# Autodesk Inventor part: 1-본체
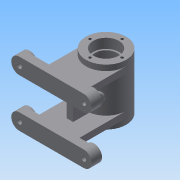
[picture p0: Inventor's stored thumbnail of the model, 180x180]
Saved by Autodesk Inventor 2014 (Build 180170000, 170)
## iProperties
Created: 2015-11
Part Number: 1-본체
Material: Generic
Document SubType Name: Modeling
Designer: 106-16
Density: 1 g/cm^3
Appearance: Default
Author: 106-16
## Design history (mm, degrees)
sketch "스케치1"
  geometry: C1 r 25 at (0, 0); 1 further point
  constraints: 1 centre point, 1 coincident
  dimensions: "d0" = 50 diameter of C1
extrude "돌출1" new body sketch "스케치1" stored distance "d1" = 70; taper "d2" = 0 deg
node "작업 평면2"
  node "작업 평면1"
sketch "스케치2"
  geometry: L1 (-40, 40)-(40, 40); L2 (40, 20)-(-40, 20); L3 (-40, -20)-(40, -20); L4 (40, -40)-(-40, -40); A1 r 10 centre (40, 30) between (40, 20) and (40, 40); A2 r 10 centre (-40, 30) between (-40, 40) and (-40, 20); A3 r 10 centre (40, -30) between (40, -40) and (40, -20); A4 r 10 centre (-40, -30) between (-40, -20) and (-40, -40); 3 further points
  constraints: 8 end point, 8 point on circle, 8 tangent, 4 centre point, 3 parallel, 2 midpoint, 2 vertical alignment, 1 horizontal
  dimensions: "d5" = 80 distance of L1.start L1.end; "d6" = 10 radius of A2; "d7" = 80 distance of L3.start L3.end; "d8" = 10 radius of A4; "d9" = 40 distance from line of point (0, 0) L1; "d10" = 40 distance from line of point (0, 0) L4
extrude "돌출2" join sketch "스케치2" distance "d11" = 10; taper "d12" = 0 deg
sketch "스케치3"
  geometry: L1 (-40, 20)-(40, 20) reference; L2 (40, 40)-(-40, 40) reference; L3 (-40, -40)-(40, -40) reference; L4 (40, -20)-(-40, -20) reference; C1 r 10 at (-40, -30); C2 r 10 at (40, -30); C3 r 10 at (40, 30); C4 r 10 at (-40, 30); A1 r 10 centre (-40, -30) between (-40, -20) and (-40, -40) reference; A2 r 10 centre (40, 30) between (40, 20) and (40, 40) reference; A3 r 10 centre (-40, 30) between (-40, 40) and (-40, 20) reference; A4 r 10 centre (40, -30) between (40, -40) and (40, -20) reference; A5 r 10 centre (-40, -30) between (-40, -20) and (-40, -40) reference; 1 further point
  constraints: 4 centre point, 4 coincident
  dimensions: "d13" = 20 diameter of C1; "d14" = 20 diameter of C4; "d15" = 20 diameter of C3; "d16" = 20 diameter of C2
extrude "돌출3" join sketch "스케치3" distance "d17" = 3; taper "d18" = 0 deg
sketch "스케치4"
  geometry: L1 (40, -20)-(-40, -20) reference; L2 (40, 20)-(-40, 20) reference; L3 (-40, 40)-(40, 40) reference; L4 (-25, 20)-(-25, 28); L5 (-25, 28)-(25, 28); L6 (25, 28)-(25, 20); L7 (-25, -20)-(-25, -28); L8 (-25, -28)-(25, -28); L9 (25, -28)-(25, -20); A1 r 10 centre (-40, 30) between (-40, 40) and (-40, 20) reference; A2 r 10 centre (40, 30) between (40, 20) and (40, 40) reference; 3 further points
  constraints: 12 end point, 5 perpendicular, 4 point on line, 2 midpoint, 2 vertical alignment, 1 parallel
  dimensions: "d19" = 8 distance between parallel lines of L2 L5; "d20" = 50 distance of L4.end L5.end; "d21" = 8 distance of L7.start L7.end; "d22" = 50 distance of L7.end L8.end
extrude "돌출4" join sketch "스케치4" stored distance "d23" = 3; taper "d24" = 0 deg
node "작업 평면4"
  node "작업 평면3"
sketch "스케치5"
  geometry: L1 (40, 40)-(-40, 40) reference; L2 (-40, 20)-(40, 20) reference; L3 (40, -20)-(-40, -20) reference; L4 (-40, -40)-(40, -40) reference; L5 (-4, -20)-(-4, 20); L6 (4, 20)-(4, -20); A1 r 10 centre (-40, 30) between (-40, 40) and (-40, 20) reference; A2 r 10 centre (40, 30) between (40, 20) and (40, 40) reference; A3 r 10 centre (-40, -30) between (-40, -20) and (-40, -40) reference; A4 r 10 centre (40, -30) between (40, -40) and (40, -20) reference; 1 further point
  constraints: 4 end point, 4 point on line, 2 perpendicular
  dimensions: "d26" = 8 distance between parallel lines of L6 L5; "d27" = 4 distance from line of L5 point (0, 0)
extrude "돌출5" join sketch "스케치5" stored distance "d28" = 3; taper "d29" = 0 deg
sketch "스케치6"
  geometry: L1 (40, 20.322)-(40, 0) reference; L2 (12, 13.5)-(28, 13.5); L3 (28, 6.5)-(12, 6.5); L4 (55, 20)-(55, 70) reference; L5 (-15, 70)-(-15, 20) reference; L6 (0, 20.322)-(40, 20.322) reference; L7 (40, 20.322)-(40, 45) reference; L8 (40, 45)-(48, 45) reference; L9 (48, 45)-(48, 45) reference; L10 (40, 45)-(48, 45) reference; L11 (40, 45)-(40, 20.322) reference; L12 (40, 20.322)-(0, 20.322) reference; L13 (0, 20.322)-(0, 45) reference; L14 (-8, 45)-(0, 45) reference; L15 (-8, 45)-(-8, 45) reference; L16 (-8, 45)-(0, 45) reference; L17 (0, 45)-(0, 20.322) reference; L18 (40, -23)-(60, -23) reference; A1 r 3.5 centre (28, 10) between (28, 6.5) and (28, 13.5); A2 r 3.5 centre (12, 10) between (12, 13.5) and (12, 6.5); 3 further points
  constraints: 4 end point, 4 point on circle, 4 tangent, 2 centre point, 2 midpoint, 1 parallel, 1 perpendicular, 1 vertical alignment
  dimensions: "d30" = 23 dimension on A2 A1; "d31" = 3.5 radius of A1; "d32" = 33 vertical distance of A1.centre L18.start
extrude "돌출6" cut sketch "스케치6" stored distance "d33" = 3; taper "d34" = 0 deg
node "작업 평면5"
sketch "스케치7"
  geometry: L1 (-25, -35)-(25, -35) reference; 2 further points
  constraints: 1 other
  dimensions: "d35" = 25 horizontal distance of point (0, 0) L1.start; "d36" = 35 distance from line of point (0, 0) L1
feature "엠보싱1" sketch "스케치7" dims "d37" = 0.5, "d38" = 0
node "작업 평면7"
  node "작업 평면6"
sketch "스케치8"
  geometry: C1 r 5 at (0, 0); 1 further point
  constraints: 1 centre point, 1 coincident
  dimensions: "d40" = 10 diameter of C1
extrude "돌출7" join sketch "스케치8" stored distance "d41" = 3; taper "d42" = 0 deg
node "작업 평면8"
sketch "스케치9"
  geometry: L1 (0, 0)-(25, 0); L2 (0, 0)-(12.5, -21.651); L3 (0, 0)-(0, -25); A1 r 25 centre (0, 0) between (25, 0) and (12.5, -21.651) reference; 2 further points
  constraints: 6 end point, 3 point on circle, 1 coincident, 1 horizontal, 1 perpendicular
  dimensions: "d44" = 30 deg angle of L2 L3
node "작업 평면10"
  node "작업 평면9"
sketch "스케치10"
  geometry: C1 r 6 at (0, 0); 1 further point
  constraints: 1 centre point, 1 coincident
  dimensions: "d46" = 12 diameter of C1
extrude "돌출8" join sketch "스케치10" stored distance "d47" = 3; taper "d48" = 0 deg
sketch "스케치11"
  geometry: C1 r 10 at (0, 0) reference; C2 r 10 at (0, -60) reference; C3 r 10 at (80, 0) reference; C4 r 10 at (80, -60) reference; 5 further points
  constraints: 4 coincident
hole "구멍1" sketch "스케치11" at (0, 0), (0, -60), (80, -60), (80, 0) diameter "d49" = 6; stored, may be unused: countersink angle "d53" = 90 deg, drill point angle "d55" = 0 deg; dims "d50" = 6, "d51" = 12, "d52" = 4, "d54" = 13
hole "구멍2" diameter "d58" = 28; stored, may be unused: countersink angle "d62" = 90 deg, drill point angle "d64" = 0 deg; dims "d56" = 10, "d57" = 10, "d59" = 6, "d60" = 32, "d61" = 12, "d63" = 13
hole "구멍3" diameter "d67" = 28; stored, may be unused: countersink angle "d71" = 90 deg, drill point angle "d73" = 0 deg; dims "d65" = 10, "d66" = 10, "d68" = 6, "d69" = 32, "d70" = 12, "d72" = 13
node "작업 평면11"
sketch "스케치12"
  geometry: L1 (-14, -23)-(14, -23) reference; L2 (14, 23)-(-14, 23) reference; L3 (14, -23)-(14, 23) reference; L4 (-14, -23)-(-14, 23) reference; L5 (0, 21)-(0, -21); L6 (21, 18)-(21, -18); L7 (0, 21)-(18, 21); L8 (0, -21)-(18, -21); A1 r 3 centre (18, 18) between (21, 18) and (18, 21); A2 r 3 centre (18, -18) between (18, -21) and (21, -18); 2 further points
  constraints: 8 end point, 4 point on circle, 4 tangent, 2 centre point, 2 parallel, 2 perpendicular, 1 coincident, 1 equal radius, 1 midpoint
  dimensions: "d75" = 42 distance of L5.start L5.end; "d76" = 42 diameter of L6 L5; "d77" = 3 radius of A1
revolve "회전1" sketch "스케치12" stored, may be unused: angle "d78" = 90 deg
sketch "스케치13"
  geometry: C1 r 16 at (0, 0) reference; C2 r 25 at (0, 0) reference; A1 r 20 centre (0, 0) between (0, 20) and (20, 0); 2 further points
  constraints: 4 point on circle, 2 horizontal alignment, 2 vertical alignment, 1 centre point, 1 coincident
  dimensions: "d79" = 40 diameter of A1
hole "구멍4" sketch "스케치13" at (0, 20), (20, 0), (-20, 0), (0, -20) diameter "d80" = 3.242; stored, may be unused: countersink angle "d84" = 90 deg, drill point angle "d86" = 118 deg; dims "d81" = 8, "d82" = 4, "d83" = 2, "d85" = 10
node "작업 평면12"
node "솔리드1"
mirror "대칭1"
node "투영된 루프1"
node "투영된 루프2"
node "투영된 루프3"
node "투영된 루프4"
node "투영된 루프5"
node "투영된 루프6"
node "투영된 루프7"
node "투영된 루프8"
node "투영된 루프9"
other parameters: "d3" = 0, "d4" = -68, "d39" = 3, "d45" = 3, "d74" = 0
